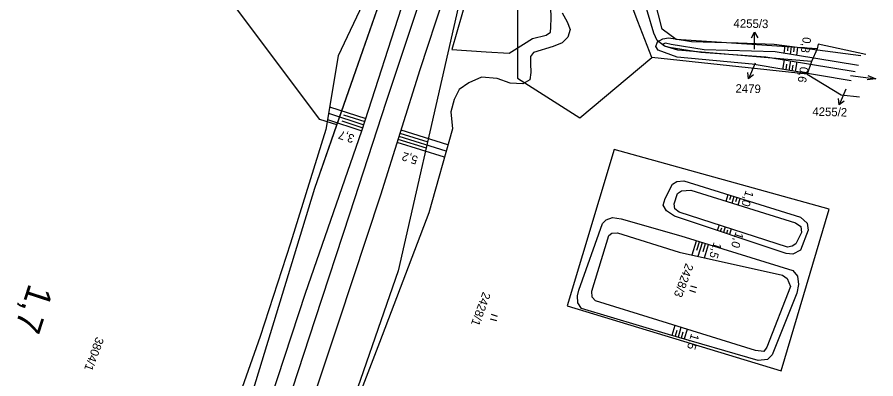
# Model space of a CAD drawing. Extents: x -659211 to -658900, y -1170600 to -1169973.
# Drawn here: x -659104.4 to -658902.5, y -1170352.4 to -1170267.3 of the extents above; entities that cross this region are included whole.
import ezdxf

# ---------------------------------------------------------------- set-up
doc = ezdxf.new("R2010")
doc.units = 0
for name, color, linetype in [('Vrstva 1', 7, 'Continuous'), ('Vrstva 48', 7, 'Continuous'), ('Vrstva 49', 7, 'Continuous'), ('Vrstva 53', 7, 'Continuous'), ('Vrstva 54', 7, 'Continuous'), ('Vrstva 55', 7, 'Continuous'), ('Vrstva 56', 7, 'Continuous'), ('Vrstva 57', 7, 'Continuous'), ('Vrstva 58', 7, 'Continuous'), ('Vrstva 7', 7, 'Continuous')]:
    doc.layers.add(name, color=color, linetype=linetype)

msp = doc.modelspace()

# ---------------------------------------------------------------- linework, layer by layer
at = {"layer": 'Vrstva 1'}
msp.add_lwpolyline([(-659008.96, -1170260.94), (-659017.62, -1170287.17), (-659026.28, -1170313.71), (-659034.33, -1170338.33), (-659039.71, -1170354.86)], dxfattribs=at)
at = {"layer": 'Vrstva 48'}
for p, q in [((-658924.07, -1170275.84), (-658923.83, -1170274.02)), ((-658923.23, -1170275.23), (-658923.08, -1170274.12)), ((-658922.58, -1170276.08), (-658922.34, -1170274.22)), ((-658921.75, -1170275.45), (-658921.6, -1170274.31)), ((-658921.1, -1170276.33), (-658920.85, -1170274.41)), ((-658924.06, -1170277.37), (-658924.44, -1170279.61)), ((-658923.47, -1170278.39), (-658923.7, -1170279.73)), ((-658922.58, -1170277.61), (-658922.96, -1170279.86)), ((-658921.99, -1170278.63), (-658922.22, -1170279.98)), ((-658921.1, -1170277.85), (-658921.48, -1170280.11)), ((-659030.93, -1170288.45), (-659022.43, -1170291.19)), ((-659031.17, -1170289.94), (-659022.89, -1170292.62)), ((-659027.69, -1170290.28), (-659022.66, -1170291.9)), ((-659031.42, -1170291.44), (-659023.35, -1170294.04)), ((-659028.03, -1170291.75), (-659023.12, -1170293.33)), ((-659007.75, -1170296.74), (-659014.38, -1170294.67)), ((-659003.12, -1170297.4), (-659014.15, -1170293.95)), ((-659003.93, -1170300.29), (-659015.05, -1170296.81)), ((-659008.17, -1170298.18), (-659014.82, -1170296.1)), ((-659003.53, -1170298.85), (-659014.6, -1170295.38)), ((-658937.72, -1170310.59), (-658937.26, -1170309.09)), ((-658936.82, -1170310.21), (-658936.54, -1170309.31)), ((-658936.29, -1170311.04), (-658935.82, -1170309.53)), ((-658935.39, -1170310.66), (-658935.11, -1170309.76)), ((-658934.86, -1170311.48), (-658934.39, -1170309.98)), ((-658939.36, -1170316.23), (-658939.79, -1170317.5)), ((-658938.82, -1170316.97), (-658939.08, -1170317.73)), ((-658937.94, -1170316.69), (-658938.36, -1170317.97)), ((-658937.4, -1170317.44), (-658937.65, -1170318.21)), ((-658936.51, -1170317.15), (-658936.94, -1170318.45)), ((-658945.72, -1170323.27), (-658944.7, -1170319.94)), ((-658944.58, -1170322.13), (-658943.98, -1170320.16)), ((-658944.26, -1170323.6), (-658943.26, -1170320.38)), ((-658943.13, -1170322.5), (-658942.55, -1170320.6)), ((-658942.79, -1170323.93), (-658941.83, -1170320.82)), ((-658949.77, -1170339.9), (-658950.44, -1170342.2)), ((-658949.32, -1170341.03), (-658949.72, -1170342.41)), ((-658948.33, -1170340.34), (-658949, -1170342.62)), ((-658947.88, -1170341.47), (-658948.28, -1170342.83)), ((-658946.9, -1170340.78), (-658947.56, -1170343.04))]:
    msp.add_line(p, q, dxfattribs=at)
at = {"layer": 'Vrstva 49'}
for p, q in [((-659009.67, -1170279.64), (-658998.04, -1170244.5)), ((-659023.35, -1170294.04), (-659010.66, -1170254.73)), ((-658997.13, -1170257.19), (-659002.19, -1170274.95)), ((-658978.86, -1170267.46), (-658979.11, -1170258.88)), ((-659022.5, -1170262.76), (-659028.97, -1170276.46)), ((-658976.27, -1170266.34), (-658975.07, -1170268.46)), ((-658978.9, -1170269.64), (-658978.86, -1170267.46)), ((-658975.07, -1170268.46), (-658974.41, -1170270.2)), ((-658980.04, -1170271.55), (-658979.02, -1170270.87)), ((-658979.02, -1170270.87), (-658978.9, -1170269.64)), ((-658974.41, -1170270.2), (-658974.94, -1170272.02)), ((-658985.36, -1170273.71), (-658983.24, -1170272.36)), ((-658983.24, -1170272.36), (-658980.04, -1170271.55)), ((-658974.94, -1170272.02), (-658976.25, -1170273.39)), ((-658953.87, -1170273.16), (-658952.58, -1170272.45)), ((-658952.58, -1170272.45), (-658951.27, -1170272.17)), ((-658951.27, -1170272.17), (-658950.15, -1170272.35)), ((-658950.15, -1170272.35), (-658945.87, -1170273.08)), ((-659002.19, -1170274.95), (-658994.15, -1170275.45)), ((-658988.74, -1170275.79), (-658985.36, -1170273.71)), ((-658978.41, -1170274.21), (-658983, -1170275.6)), ((-658976.25, -1170273.39), (-658978.41, -1170274.21)), ((-658954.26, -1170274.2), (-658953.87, -1170273.16)), ((-658953.65, -1170275.05), (-658954.26, -1170274.2)), ((-658949.2, -1170276.72), (-658953.65, -1170275.05)), ((-658951.95, -1170273.42), (-658952.58, -1170273.66)), ((-658952.58, -1170273.66), (-658952.22, -1170274.1)), ((-658952.22, -1170274.1), (-658951.06, -1170274.38)), ((-658950.62, -1170273.78), (-658951.95, -1170273.42)), ((-658951.06, -1170274.38), (-658943.62, -1170275.53)), ((-658942.89, -1170274.98), (-658950.62, -1170273.78)), ((-658945.87, -1170273.08), (-658934.9, -1170273.37)), ((-658926.14, -1170275.5), (-658942.89, -1170274.98)), ((-658934.9, -1170273.37), (-658926.38, -1170273.69)), ((-658926.38, -1170273.69), (-658906.05, -1170276.33)), ((-659028.97, -1170276.46), (-659031.8, -1170293.79)), ((-658994.15, -1170275.45), (-658988.74, -1170275.79)), ((-658983, -1170275.6), (-658983.69, -1170276.6)), ((-658983.69, -1170276.6), (-658983.68, -1170278.23)), ((-658931.61, -1170278.4), (-658949.2, -1170276.72)), ((-658943.62, -1170275.53), (-658928.38, -1170276.67)), ((-658928.38, -1170276.67), (-658907.4, -1170280.07)), ((-658906.6, -1170278.72), (-658926.14, -1170275.5)), ((-658983.68, -1170278.23), (-658983.66, -1170280.32)), ((-658908.34, -1170282.32), (-658931.61, -1170278.4)), ((-659018.91, -1170309.14), (-659009.67, -1170279.64)), ((-658983.66, -1170280.32), (-658983.84, -1170282.09)), ((-658998.23, -1170282.8), (-659000.47, -1170284.37)), ((-658995.21, -1170281.47), (-658998.23, -1170282.8)), ((-658991.52, -1170281.73), (-658995.21, -1170281.47)), ((-658988.49, -1170282.89), (-658991.52, -1170281.73)), ((-658985.52, -1170282.98), (-658988.49, -1170282.89)), ((-658983.84, -1170282.09), (-658985.52, -1170282.98)), ((-659000.47, -1170284.37), (-659001.67, -1170286.67)), ((-659001.67, -1170286.67), (-659002.43, -1170289.62)), ((-659002.43, -1170289.62), (-659002.05, -1170293.59)), ((-659031.8, -1170293.79), (-659040.14, -1170320.54)), ((-659036.63, -1170332.27), (-659023.35, -1170294.04)), ((-659002.05, -1170293.59), (-659007.6, -1170313.33)), ((-658952.07, -1170309.99), (-658950.33, -1170306.62)), ((-658950.33, -1170306.62), (-658949.33, -1170306.02)), ((-658949.33, -1170306.02), (-658947.66, -1170305.87)), ((-658947.66, -1170305.87), (-658920.22, -1170314.37)), ((-659028.79, -1170339.01), (-659018.91, -1170309.14)), ((-658949.94, -1170311.21), (-658949.14, -1170308.85)), ((-658949.14, -1170308.85), (-658948.17, -1170308.21)), ((-658948.17, -1170308.21), (-658945.97, -1170308.02)), ((-658945.97, -1170308.02), (-658921.36, -1170315.69)), ((-658952.51, -1170311.54), (-658952.07, -1170309.99)), ((-658949.74, -1170312.41), (-658949.94, -1170311.21)), ((-659007.6, -1170313.33), (-659019.2, -1170343.88)), ((-658951.76, -1170312.91), (-658952.51, -1170311.54)), ((-658949.86, -1170314.13), (-658951.76, -1170312.91)), ((-658948.78, -1170313.19), (-658949.74, -1170312.41)), ((-658923.31, -1170321.42), (-658948.78, -1170313.19)), ((-658966.77, -1170315.86), (-658965.91, -1170315.02)), ((-658965.91, -1170315.02), (-658964.41, -1170314.5)), ((-658964.41, -1170314.5), (-658962.38, -1170314.75)), ((-658962.38, -1170314.75), (-658948.36, -1170318.81)), ((-658923.58, -1170322.92), (-658949.86, -1170314.13)), ((-658920.22, -1170314.37), (-658918.67, -1170315.82)), ((-658972.36, -1170331.54), (-658966.77, -1170315.86)), ((-658921.36, -1170315.69), (-658920.14, -1170316.61)), ((-658918.38, -1170317.41), (-658920.21, -1170322.12)), ((-658920.14, -1170316.61), (-658920, -1170317.99)), ((-658918.67, -1170315.82), (-658918.38, -1170317.41)), ((-658969.28, -1170331.79), (-658965.3, -1170318.73)), ((-658965.3, -1170318.73), (-658964.56, -1170318.13)), ((-658964.56, -1170318.13), (-658963.28, -1170318.04)), ((-658963.28, -1170318.04), (-658948.72, -1170322.6)), ((-658948.36, -1170318.81), (-658922.05, -1170326.92)), ((-658920, -1170317.99), (-658921.31, -1170320.68)), ((-659040.14, -1170320.54), (-659047.27, -1170342.43)), ((-658922.2, -1170321.22), (-658923.31, -1170321.42)), ((-658921.31, -1170320.68), (-658922.2, -1170321.22)), ((-658948.72, -1170322.6), (-658924.43, -1170328.03)), ((-658921.99, -1170323.12), (-658923.58, -1170322.92)), ((-658920.21, -1170322.12), (-658921.99, -1170323.12)), ((-658922.05, -1170326.92), (-658920.93, -1170328.29)), ((-658924.43, -1170328.03), (-658923.39, -1170328.78)), ((-658923.39, -1170328.78), (-658922.55, -1170330.68)), ((-658920.93, -1170328.29), (-658920.65, -1170330.21)), ((-658972.66, -1170332.93), (-658972.36, -1170331.54)), ((-658922.55, -1170330.68), (-658928.16, -1170344.95)), ((-658920.65, -1170330.21), (-658921.08, -1170332.3)), ((-659048.64, -1170368.95), (-659036.63, -1170332.27)), ((-658972.57, -1170334.56), (-658972.66, -1170332.93)), ((-658969.21, -1170333.23), (-658969.28, -1170331.79)), ((-658968.44, -1170334.05), (-658969.21, -1170333.23)), ((-658921.08, -1170332.3), (-658926.9, -1170346.77)), ((-658971.75, -1170335.85), (-658972.57, -1170334.56)), ((-658953.77, -1170338.66), (-658968.44, -1170334.05)), ((-658951.27, -1170341.96), (-658971.75, -1170335.85)), ((-659039.58, -1170371.56), (-659028.79, -1170339.01)), ((-658930.82, -1170345.74), (-658953.77, -1170338.66)), ((-659047.27, -1170342.43), (-659059.83, -1170377.86)), ((-658930.19, -1170348.13), (-658951.27, -1170341.96)), ((-659019.2, -1170343.88), (-659030.4, -1170372.76)), ((-658928.16, -1170344.95), (-658928.81, -1170345.97)), ((-658928.81, -1170345.97), (-658930.82, -1170345.74)), ((-658926.9, -1170346.77), (-658927.97, -1170347.89)), ((-658927.97, -1170347.89), (-658930.19, -1170348.13))]:
    msp.add_line(p, q, dxfattribs=at)
at = {"layer": 'Vrstva 53'}
for points in [[(-658962.46, -1170159.99), (-658968.43, -1170175.7), (-658976.4, -1170188.09), (-658983.99, -1170202.81), (-658991.44, -1170224.37), (-659014.8, -1170327)], [(-659034.44, -1170307.59), (-659029.23, -1170292.66), (-659006.6, -1170227.81), (-659002.13, -1170227.74)], [(-659081.48, -1170461.88), (-659034.44, -1170307.59)], [(-659014.8, -1170327), (-659040.68, -1170401.69), (-659069.54, -1170465.79), (-659067.16, -1170471.54), (-659071.55, -1170492.02), (-659079.75, -1170512.52), (-659099.17, -1170514.57)]]:
    msp.add_lwpolyline(points, dxfattribs=at)
at = {"layer": 'Vrstva 54'}
for p, q in [((-658931.76, -1170272.19), (-658931.01, -1170270.89)), ((-658931.25, -1170280.92), (-658932.45, -1170281.83)), ((-658909.94, -1170287.07), (-658911.13, -1170287.97))]:
    msp.add_line(p, q, dxfattribs=at)
for points in [[(-658931.01, -1170274.89), (-658931.01, -1170270.89), (-658930.26, -1170272.19)], [(-658930.9, -1170278.14), (-658932.45, -1170281.83), (-658932.63, -1170280.34)], [(-658909.59, -1170284.29), (-658911.13, -1170287.97), (-658911.32, -1170286.48)]]:
    msp.add_lwpolyline(points, dxfattribs=at)
at = {"layer": 'Vrstva 55'}
for points in [[(-658991.44, -1170224.37), (-659014.8, -1170327), (-659040.68, -1170401.69), (-659069.54, -1170465.79), (-659067.16, -1170471.54), (-659071.55, -1170492.02), (-659079.75, -1170512.52)], [(-658984.87, -1170222.8), (-658986.8, -1170241.19), (-658986.8, -1170281.68), (-658972.14, -1170291), (-658955.16, -1170276.81)], [(-659085.15, -1170471.18), (-659081.48, -1170461.88), (-659034.44, -1170307.59), (-659006.6, -1170227.81)], [(-658917.65, -1170277.74), (-658918.62, -1170280.76), (-658955.16, -1170276.81), (-658958.43, -1170268.32), (-658964.45, -1170252.47), (-658938.23, -1170241.83), (-658934.65, -1170250.6)], [(-659029.23, -1170292.66), (-659033.26, -1170291.41), (-659066.04, -1170247.67)], [(-658904.88, -1170276.14), (-658916.05, -1170273.67), (-658916.29, -1170274.79), (-658949.49, -1170272.55), (-658952.77, -1170270.16), (-658957.89, -1170249.82)], [(-658916.29, -1170274.79), (-658917.65, -1170277.74), (-658949.1, -1170275.11), (-658952.21, -1170274.15), (-658953.94, -1170272.84), (-658954.67, -1170271.1), (-658960.68, -1170250.95)]]:
    msp.add_lwpolyline(points, dxfattribs=at)
msp.add_lwpolyline([(-658913.5, -1170312.54), (-658964.01, -1170298.49), (-658975.07, -1170335.22), (-658924.75, -1170350.53)], close=True, dxfattribs=at)
at = {"layer": 'Vrstva 56'}
msp.add_lwpolyline([(-658918.62, -1170280.76), (-658910.66, -1170285.62), (-658906.32, -1170286.1)], dxfattribs=at)
at = {"layer": 'Vrstva 58'}
for p, q in [((-658908.45, -1170281.05), (-658902.5, -1170281.84)), ((-658946.31, -1170331.56), (-658944.88, -1170332.01)), ((-658944.58, -1170331.05), (-658946.02, -1170330.61)), ((-658991.44, -1170337.76), (-658992.87, -1170337.31)), ((-658993.16, -1170338.27), (-658991.73, -1170338.71))]:
    msp.add_line(p, q, dxfattribs=at)
msp.add_lwpolyline([(-658904.42, -1170281.08), (-658902.5, -1170281.84), (-658904.55, -1170282.07)], dxfattribs=at)

# ---------------------------------------------------------------- texts
at = {"layer": 'Vrstva 48'}
for s, rotation, p in [('0,8', 262.589, (-658919.67, -1170271.91)), ('0,6', 260.4553, (-658920.29, -1170278.87)), ('3,7', 162.1124, (-659024.94, -1170295.11)), ('5,2', 162.6231, (-659010.02, -1170300.14)), ('1,0', 252.7717, (-658933.07, -1170307.96)), ('1,0', 251.5121, (-658935.42, -1170317.72)), ('1,5', 252.8791, (-658940.6, -1170320.17)), ('1,5', 253.6805, (-658945.9, -1170341.64))]:
    msp.add_text(s, height=2, rotation=rotation, dxfattribs=at).set_placement(p)
at = {"layer": 'Vrstva 57'}
for s, rotation, p in [('4255/3', 358.9624, (-658935.98, -1170269.76)), ('2479', 358.9624, (-658935.51, -1170285.09)), ('4255/2', 358.47, (-658917.45, -1170290.5)), ('2428/3', 249.6006, (-658947.19, -1170325.1)), ('2428/1', 249.6006, (-658994.88, -1170331.83)), ('3804/1', 249.6006, (-659085.83, -1170342.42))]:
    msp.add_text(s, height=2, rotation=rotation, dxfattribs=at).set_placement(p)
at = {"layer": 'Vrstva 7'}
msp.add_text('1,7', height=6, rotation=251.9711, dxfattribs=at).set_placement((-659101.6, -1170329.82))

doc.saveas('drawing.dxf')
